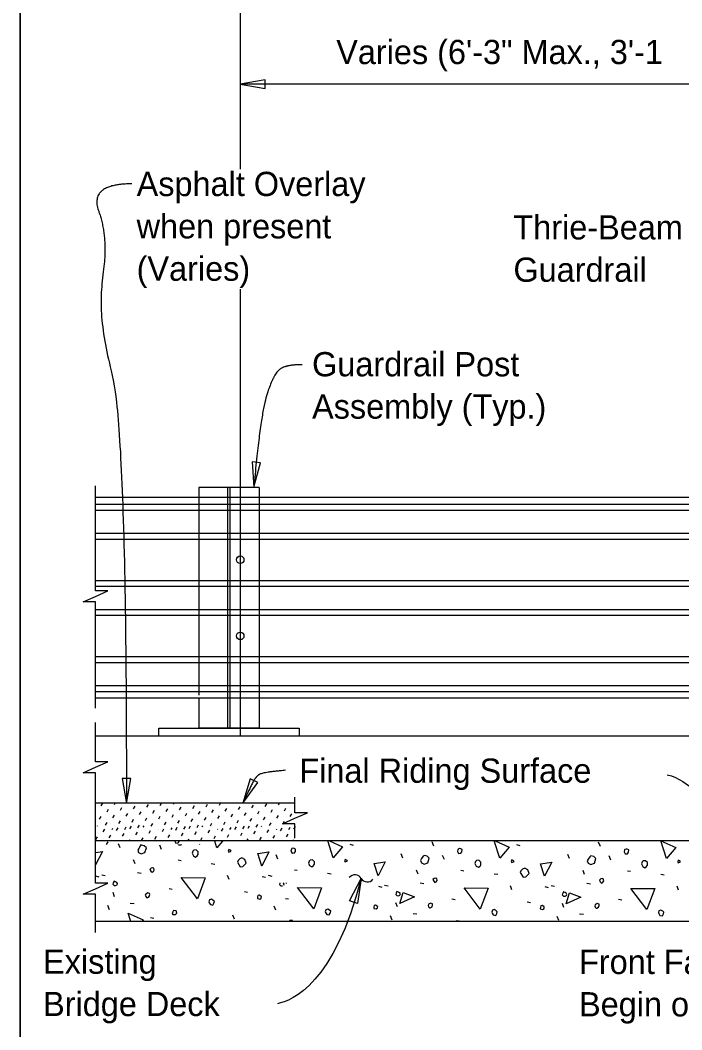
# Model space of a CAD drawing. Extents: x 0 to 41.1, y 0 to 25.9.
# Drawn here: x 0 to 5.5, y 5.42 to 13.82 of the extents above; entities that cross this region are included whole.
import ezdxf

# ---------------------------------------------------------------- set-up
doc = ezdxf.new("R2010")
doc.units = 0
for name, color, linetype in [('Dimension', 7, 'Continuous'), ('ExistSuperStruct', 7, 'Continuous'), ('Miscellaneous', 7, 'Continuous'), ('Miscellaneous1', 7, 'Continuous'), ('SteelMisc', 7, 'Continuous'), ('SteelMisc_h', 7, 'Continuous'), ('TextStructures', 7, 'Continuous')]:
    doc.layers.add(name, color=color, linetype=linetype)

msp = doc.modelspace()

# ---------------------------------------------------------------- linework, layer by layer
at = {"layer": 'Dimension'}
msp.add_line((13.3576, 13.2855), (1.8291, 13.2855), dxfattribs=at)
for points in [[(0, 0), (41.0506, 0), (41.0506, 25.9461), (0, 25.9461)], [(1.8291, 13.2855), (2.0373, 13.2502), (2.0373, 13.3208)], [(1.9418, 9.9338), (1.9976, 10.1375), (1.9274, 10.1445)], [(0.884, 7.306), (0.9193, 7.5143), (0.8488, 7.5143)], [(1.8496, 7.3086), (1.9742, 7.4791), (1.9111, 7.5107)], [(2.8349, 6.682), (2.8044, 6.473), (2.7373, 6.4947)]]:
    msp.add_lwpolyline(points, close=True, dxfattribs=at)
for points in [[(0.6262, 8.0985), (0.6262, 8.9817), (0.5229, 8.9817), (0.6262, 9.0267), (0.7296, 9.0717), (0.6262, 9.0717), (0.6262, 9.9446)], [(0.6262, 6.994), (0.6262, 7.5611), (0.5229, 7.5611), (0.6262, 7.6061), (0.7296, 7.6511), (0.6262, 7.6511), (0.6262, 7.9771)], [(2.2842, 7.0165), (2.2842, 7.1374), (2.1809, 7.1374), (2.2842, 7.1824), (2.3875, 7.2274), (2.2842, 7.2274), (2.2842, 7.358)], [(0.6262, 6.2316), (0.6262, 6.5516), (0.5229, 6.5516), (0.6262, 6.5966), (0.7296, 6.6416), (0.6262, 6.6416), (0.6262, 6.994)]]:
    msp.add_lwpolyline(points, dxfattribs=at)
for centre, start, end in [((2.7825, 6.6524), 30.00813, 141.73535), ((2.8857, 6.712), 210.00813, 321.73535)]:
    msp.add_arc(centre, 0.0596, start, end, dxfattribs=at)
for points, degree in [([(0.9269, 12.4562), (0.5696, 12.4558), (0.7356, 11.9999), (0.6366, 11.3563), (0.884, 10.4229), (0.884, 7.306)], 2), ([(2.3429, 10.9528), (2.2028, 10.9528), (2.1032, 10.8686), (1.9973, 10.5383), (1.9418, 9.9338)], 2), ([(2.2058, 7.581), (2.0322, 7.5656), (1.958, 7.5342), (1.8924, 7.3943), (1.8495, 7.3086)], 2), ([(5.3781, 7.5447), (5.4744, 7.5208), (5.6296, 7.4038), (5.7185, 7.3059), (5.9286, 6.9969)], 3), ([(2.834, 6.6822), (2.6134, 5.8085), (2.2614, 5.6668), (2.1395, 5.6403)], 3)]:
    msp.add_open_spline(points, degree=degree, dxfattribs=at)
at = {"layer": 'ExistSuperStruct'}
for p, q in [((0.6262, 7.8689), (8.9932, 7.8689)), ((2.2842, 7.3073), (0.6262, 7.3073)), ((8.9932, 6.994), (0.6262, 6.994)), ((0.6262, 6.3273), (8.9932, 6.3273))]:
    msp.add_line(p, q, dxfattribs=at)
at = {"layer": 'Miscellaneous'}
for p, q in [((1.8291, 15.3365), (1.8291, 12.5773)), ((1.8291, 11.5818), (1.8291, 7.8713)), ((0.6731, 7.2848), (0.6861, 7.3072)), ((0.7838, 7.2978), (0.7893, 7.3073)), ((1.1645, 7.2878), (1.1758, 7.3073)), ((1.2751, 7.3008), (1.2789, 7.3073)), ((1.6559, 7.2909), (1.6654, 7.3073)), ((1.7665, 7.3038), (1.7685, 7.3073)), ((2.0366, 7.2809), (2.0495, 7.3033)), ((2.1472, 7.2939), (2.155, 7.3073)), ((2.2579, 7.3068), (2.2581, 7.3073)), ((0.722, 7.236), (0.7349, 7.2584)), ((0.8326, 7.2489), (0.8456, 7.2713)), ((0.8814, 7.2001), (0.8944, 7.2225)), ((0.9432, 7.2619), (0.9562, 7.2843)), ((0.9921, 7.2131), (1.005, 7.2355)), ((1.0539, 7.2749), (1.0668, 7.2973)), ((1.1027, 7.226), (1.1157, 7.2484)), ((1.2133, 7.239), (1.2263, 7.2614)), ((1.324, 7.252), (1.3369, 7.2744)), ((1.3728, 7.2031), (1.3858, 7.2255)), ((1.4346, 7.2649), (1.4476, 7.2873)), ((1.4834, 7.2161), (1.4964, 7.2385)), ((1.5452, 7.2779), (1.5582, 7.3003)), ((1.5941, 7.2291), (1.607, 7.2515)), ((1.7047, 7.242), (1.7177, 7.2644)), ((1.8153, 7.255), (1.8283, 7.2774)), ((1.8642, 7.2062), (1.8771, 7.2285)), ((1.926, 7.268), (1.9389, 7.2903)), ((1.9748, 7.2191), (1.9878, 7.2415)), ((2.0854, 7.2321), (2.0984, 7.2545)), ((2.1961, 7.245), (2.209, 7.2674)), ((2.2449, 7.1962), (2.2579, 7.2186)), ((0.6602, 7.1742), (0.6731, 7.1966)), ((0.709, 7.1254), (0.722, 7.1477)), ((0.7708, 7.1872), (0.7838, 7.2095)), ((0.8196, 7.1383), (0.8326, 7.1607)), ((0.9303, 7.1513), (0.9432, 7.1737)), ((1.0409, 7.1642), (1.0539, 7.1866)), ((1.0897, 7.1154), (1.1027, 7.1378)), ((1.1515, 7.1772), (1.1645, 7.1996)), ((1.2004, 7.1284), (1.2133, 7.1508)), ((1.2622, 7.1902), (1.2751, 7.2126)), ((1.311, 7.1413), (1.324, 7.1637)), ((1.4216, 7.1543), (1.4346, 7.1767)), ((1.5323, 7.1673), (1.5452, 7.1897)), ((1.5811, 7.1184), (1.5941, 7.1408)), ((1.6429, 7.1802), (1.6559, 7.2026)), ((1.6917, 7.1314), (1.7047, 7.1538)), ((1.7535, 7.1932), (1.7665, 7.2156)), ((1.8024, 7.1444), (1.8153, 7.1667)), ((1.913, 7.1573), (1.926, 7.1797)), ((2.0236, 7.1703), (2.0366, 7.1927)), ((2.0725, 7.1214), (2.0854, 7.1438)), ((2.1343, 7.1832), (2.1472, 7.2056)), ((2.1831, 7.1344), (2.1961, 7.1568)), ((2.2937, 7.1474), (2.2938, 7.1476)), ((0.6419, 7.1175), (0.6427, 7.119)), ((0.6907, 7.0686), (0.7037, 7.091)), ((0.7647, 7.0883), (0.7708, 7.0989)), ((0.8013, 7.0816), (0.8143, 7.104)), ((0.8502, 7.0328), (0.8631, 7.0551)), ((0.8685, 7.0895), (0.8814, 7.1119)), ((0.912, 7.0945), (0.9249, 7.1169)), ((0.9608, 7.0457), (0.9738, 7.0681)), ((0.9791, 7.1024), (0.9921, 7.1248)), ((1.0226, 7.1075), (1.0292, 7.119)), ((1.0714, 7.0587), (1.0844, 7.0811)), ((1.1512, 7.0883), (1.1515, 7.089)), ((1.1821, 7.0716), (1.195, 7.094)), ((1.2543, 7.0883), (1.2622, 7.1019)), ((1.2927, 7.0846), (1.3056, 7.107)), ((1.3415, 7.0358), (1.3545, 7.0582)), ((1.3598, 7.0925), (1.3728, 7.1149)), ((1.4033, 7.0976), (1.4157, 7.119)), ((1.4522, 7.0487), (1.4651, 7.0711)), ((1.4705, 7.1055), (1.4834, 7.1279)), ((1.514, 7.1105), (1.5188, 7.119)), ((1.5628, 7.0617), (1.5757, 7.0841)), ((1.6408, 7.0883), (1.6429, 7.092)), ((1.6734, 7.0747), (1.6864, 7.0971)), ((1.7439, 7.0883), (1.7535, 7.105)), ((1.7841, 7.0876), (1.797, 7.11)), ((1.8329, 7.0388), (1.8458, 7.0612)), ((1.8512, 7.0955), (1.8642, 7.1179)), ((1.8947, 7.1006), (1.9053, 7.119)), ((1.9435, 7.0518), (1.9565, 7.0741)), ((1.9618, 7.1085), (1.9748, 7.1309)), ((2.0053, 7.1136), (2.0085, 7.119)), ((2.0542, 7.0647), (2.0671, 7.0871)), ((2.1304, 7.0883), (2.1343, 7.095)), ((2.1648, 7.0777), (2.1777, 7.1001)), ((2.2136, 7.0288), (2.2266, 7.0512)), ((2.2335, 7.0883), (2.2449, 7.108)), ((2.2754, 7.0906), (2.2884, 7.113)), ((0.6289, 7.0068), (0.6419, 7.0292)), ((0.7184, 6.9645), (0.7314, 6.9869)), ((0.7395, 7.0198), (0.7525, 7.0422)), ((0.8301, 6.9357), (0.816, 6.971)), ((0.9048, 6.994), (0.912, 7.0063)), ((1.0096, 6.9969), (1.0226, 7.0193)), ((1.1203, 7.0098), (1.1332, 7.0322)), ((1.2309, 7.0228), (1.2439, 7.0452)), ((1.2913, 6.994), (1.2927, 6.9964)), ((1.3944, 6.994), (1.4033, 7.0093)), ((1.4908, 6.9633), (1.4929, 6.967)), ((1.501, 6.9999), (1.514, 7.0223)), ((1.6116, 7.0129), (1.6246, 7.0353)), ((1.7223, 7.0258), (1.7352, 7.0482)), ((1.7809, 6.994), (1.7841, 6.9994)), ((1.884, 6.994), (1.8947, 7.0123)), ((1.9924, 7.0029), (2.0053, 7.0253)), ((2.103, 7.0159), (2.1159, 7.0383)), ((2.2705, 6.994), (2.2754, 7.0024)), ((2.7398, 6.9668), (2.768, 6.9598)), ((3.438, 6.9509), (3.4239, 6.9863)), ((4.8227, 6.9474), (4.8086, 6.9827)), ((1.0011, 6.9633), (1.0015, 6.964)), ((1.1742, 6.9239), (1.16, 6.9593)), ((3.1817, 6.8502), (3.1676, 6.8855)), ((4.1244, 6.9633), (4.1527, 6.9562)), ((0.9556, 6.8031), (0.9432, 6.8367)), ((1.3121, 6.8356), (1.3368, 6.832)), ((1.5878, 6.8073), (1.6179, 6.802)), ((2.1411, 6.8419), (2.127, 6.8773)), ((3.5258, 6.8384), (3.5116, 6.8738)), ((4.5664, 6.8466), (4.5522, 6.882)), ((4.9105, 6.8349), (4.8963, 6.8702)), ((0.9744, 6.7313), (1.0045, 6.7259)), ((2.279, 6.7536), (2.3037, 6.75)), ((2.5548, 6.7253), (2.5848, 6.72)), ((3.3072, 6.7176), (3.2948, 6.7512)), ((3.6637, 6.75), (3.6884, 6.7465)), ((3.9394, 6.7217), (3.9695, 6.7164)), ((4.6919, 6.714), (4.6795, 6.7476)), ((5.0483, 6.7465), (5.0731, 6.7429)), ((5.3241, 6.7182), (5.3542, 6.7129)), ((0.6257, 6.703), (0.6539, 6.6959)), ((0.6781, 6.7129), (0.7064, 6.7059)), ((1.7363, 6.6729), (1.724, 6.7065)), ((2.0103, 6.6994), (2.0386, 6.6924)), ((2.0627, 6.7094), (2.091, 6.7023)), ((3.326, 6.6457), (3.3561, 6.6404)), ((4.7107, 6.6422), (4.7408, 6.6369)), ((0.7841, 6.5304), (0.7718, 6.5639)), ((1.2378, 6.5987), (1.2643, 6.5934)), ((1.8636, 6.5739), (1.8901, 6.5686)), ((2.9773, 6.6174), (3.0055, 6.6104)), ((3.0297, 6.6274), (3.058, 6.6203)), ((4.0879, 6.5874), (4.0756, 6.621)), ((4.3619, 6.6139), (4.3902, 6.6068)), ((4.4143, 6.6239), (4.4426, 6.6168)), ((5.4726, 6.5838), (5.4602, 6.6174)), ((0.9143, 6.4767), (0.9461, 6.4732)), ((2.2047, 6.5167), (2.2313, 6.5114)), ((3.1357, 6.4448), (3.1234, 6.4784)), ((3.5894, 6.5131), (3.6159, 6.5078)), ((4.2152, 6.4884), (4.2417, 6.4831)), ((4.5204, 6.4413), (4.508, 6.4749)), ((4.9741, 6.5096), (5.0006, 6.5043)), ((0.7417, 6.4208), (0.7276, 6.4561)), ((2.1264, 6.4172), (2.1122, 6.4526)), ((3.2659, 6.3912), (3.2977, 6.3876)), ((4.6506, 6.3876), (4.6824, 6.3841)), ((1.0823, 6.3583), (1.1105, 6.3512)), ((1.7805, 6.3423), (1.7664, 6.3777)), ((3.0933, 6.3352), (3.0792, 6.3706)), ((4.478, 6.3317), (4.4638, 6.367))]:
    msp.add_line(p, q, dxfattribs=at)
for points in [[(1.2841, 6.9906), (1.2926, 6.9752), (1.3121, 6.977), (1.3209, 6.9893), (1.321, 6.9906)], [(1.6356, 6.9363), (1.6179, 6.9906)], [(1.6815, 6.9906), (1.6356, 6.9363)], [(2.6025, 6.8543), (2.5571, 6.994)], [(2.5709, 6.994), (2.6803, 6.9462), (2.6025, 6.8543)], [(3.9872, 6.8508), (3.9406, 6.994)], [(3.9475, 6.994), (4.065, 6.9427), (3.9872, 6.8508)], [(5.3718, 6.8472), (5.3241, 6.994), (5.4496, 6.9392), (5.3718, 6.8472)], [(0.6262, 6.8981), (0.6834, 6.9056), (0.6262, 6.7947)], [(0.9839, 6.8986), (1.0069, 6.8862), (1.0369, 6.8986), (1.0493, 6.9357), (1.0316, 6.9534), (1.0086, 6.9587), (0.998, 6.9516), (0.9857, 6.9322), (0.9768, 6.9162), (0.9839, 6.8986)], [(1.3161, 6.9633), (1.3172, 6.9609), (1.3148, 6.9633)], [(1.3172, 6.9609), (1.3384, 6.9609), (1.3408, 6.9633)], [(1.4287, 6.8921), (1.4394, 6.8709), (1.457, 6.8603), (1.4712, 6.8709), (1.4782, 6.8815), (1.4782, 6.9027), (1.4623, 6.9186), (1.4429, 6.9169), (1.434, 6.908), (1.4287, 6.8921)], [(1.7346, 6.901), (1.754, 6.9098), (1.7469, 6.9169), (1.7346, 6.9222), (1.7293, 6.9098), (1.7346, 6.901)], [(2.0079, 6.7854), (1.9744, 6.8897), (2.0681, 6.9021), (2.0079, 6.7854)], [(2.2507, 6.9091), (2.2595, 6.8932), (2.279, 6.895), (2.2878, 6.9073), (2.2896, 6.9268), (2.2772, 6.9321), (2.2684, 6.9339), (2.2578, 6.9303), (2.2542, 6.9268), (2.2507, 6.9091)], [(3.6354, 6.9056), (3.6442, 6.8897), (3.6637, 6.8914), (3.6725, 6.9038), (3.6743, 6.9233), (3.6619, 6.9286), (3.6531, 6.9303), (3.6425, 6.9268), (3.6389, 6.9233), (3.6354, 6.9056)], [(5.0201, 6.902), (5.0289, 6.8861), (5.0483, 6.8879), (5.0572, 6.9003), (5.059, 6.9197), (5.0466, 6.925), (5.0377, 6.9268), (5.0271, 6.9233), (5.0236, 6.9197), (5.0201, 6.902)], [(1.8053, 6.8161), (1.8283, 6.779), (1.8512, 6.7807), (1.8601, 6.7896), (1.8795, 6.809), (1.8672, 6.8391), (1.8424, 6.8532), (1.8247, 6.8462), (1.8106, 6.832), (1.8053, 6.8161)], [(2.3957, 6.8101), (2.4063, 6.7889), (2.4239, 6.7783), (2.4381, 6.7889), (2.4452, 6.7995), (2.4452, 6.8207), (2.4293, 6.8366), (2.4098, 6.8349), (2.401, 6.826), (2.3957, 6.8101)], [(2.7015, 6.819), (2.7209, 6.8278), (2.7139, 6.8349), (2.7015, 6.8402), (2.6962, 6.8278), (2.7015, 6.819)], [(2.9749, 6.7034), (2.9413, 6.8077), (3.035, 6.8201), (2.9749, 6.7034)], [(3.3355, 6.813), (3.3585, 6.8007), (3.3885, 6.813), (3.4009, 6.8502), (3.3832, 6.8678), (3.3602, 6.8731), (3.3496, 6.8661), (3.3373, 6.8466), (3.3284, 6.8307), (3.3355, 6.813)], [(3.7803, 6.8066), (3.7909, 6.7854), (3.8086, 6.7748), (3.8228, 6.7854), (3.8298, 6.796), (3.8298, 6.8172), (3.8139, 6.8331), (3.7945, 6.8313), (3.7856, 6.8225), (3.7803, 6.8066)], [(4.0862, 6.8154), (4.1056, 6.8243), (4.0985, 6.8313), (4.0862, 6.8366), (4.0809, 6.8243), (4.0862, 6.8154)], [(4.3595, 6.6999), (4.326, 6.8042), (4.4196, 6.8166), (4.3595, 6.6999)], [(4.7202, 6.8095), (4.7431, 6.7971), (4.7732, 6.8095), (4.7856, 6.8466), (4.7679, 6.8643), (4.7449, 6.8696), (4.7343, 6.8625), (4.7219, 6.8431), (4.7131, 6.8272), (4.7202, 6.8095)], [(5.165, 6.803), (5.1756, 6.7818), (5.1933, 6.7712), (5.2074, 6.7818), (5.2145, 6.7924), (5.2145, 6.8137), (5.1986, 6.8296), (5.1792, 6.8278), (5.1703, 6.819), (5.165, 6.803)], [(5.4708, 6.8119), (5.4903, 6.8207), (5.4832, 6.8278), (5.4708, 6.8331), (5.4655, 6.8207), (5.4708, 6.8119)], [(1.0858, 6.7436), (1.0964, 6.733), (1.107, 6.7401), (1.1141, 6.7507), (1.1105, 6.7684), (1.1017, 6.7701), (1.0893, 6.7684), (1.0787, 6.7578), (1.0858, 6.7436)], [(4.1569, 6.7306), (4.1799, 6.6934), (4.2028, 6.6952), (4.2117, 6.7041), (4.2311, 6.7235), (4.2187, 6.7536), (4.194, 6.7677), (4.1763, 6.7606), (4.1622, 6.7465), (4.1569, 6.7306)], [(0.7806, 6.6246), (0.793, 6.6228), (0.8053, 6.6281), (0.8089, 6.6387), (0.8036, 6.6475), (0.793, 6.6546), (0.7806, 6.6599), (0.7735, 6.6458), (0.77, 6.6352), (0.7806, 6.6246)], [(1.4729, 6.512), (1.3386, 6.6888), (1.5383, 6.6871), (1.4729, 6.512)], [(2.1596, 6.6451), (2.1582, 6.6422), (2.1547, 6.6316), (2.1653, 6.621)], [(2.1909, 6.6271), (2.1936, 6.6352), (2.1883, 6.644), (2.1867, 6.6451)], [(2.2138, 6.6412), (2.215, 6.6451)], [(3.4374, 6.6581), (3.448, 6.6475), (3.4586, 6.6546), (3.4657, 6.6652), (3.4621, 6.6828), (3.4533, 6.6846), (3.4409, 6.6828), (3.4303, 6.6722), (3.4374, 6.6581)], [(4.8221, 6.6546), (4.8327, 6.6439), (4.8433, 6.651), (4.8504, 6.6616), (4.8468, 6.6793), (4.838, 6.6811), (4.8256, 6.6793), (4.815, 6.6687), (4.8221, 6.6546)], [(1.0504, 6.5244), (1.0575, 6.5244), (1.0717, 6.5315), (1.077, 6.5474), (1.0752, 6.5562), (1.061, 6.5633), (1.0434, 6.5527), (1.0398, 6.5421), (1.0434, 6.5315), (1.0504, 6.5244)], [(2.1653, 6.621), (2.1777, 6.6193), (2.1795, 6.6201)], [(2.4399, 6.43), (2.3055, 6.6068), (2.5053, 6.6051), (2.4399, 6.43)], [(3.1322, 6.539), (3.1446, 6.5373), (3.1569, 6.5426), (3.1605, 6.5532), (3.1552, 6.562), (3.1446, 6.5691), (3.1322, 6.5744), (3.1251, 6.5602), (3.1216, 6.5496), (3.1322, 6.539)], [(3.1546, 6.4742), (3.1828, 6.5662), (3.2765, 6.529), (3.1546, 6.4742)], [(3.8245, 6.4265), (3.6902, 6.6033), (3.8899, 6.6015), (3.8245, 6.4265)], [(4.5169, 6.5355), (4.5292, 6.5337), (4.5416, 6.539), (4.5452, 6.5496), (4.5399, 6.5585), (4.5292, 6.5655), (4.5169, 6.5708), (4.5098, 6.5567), (4.5063, 6.5461), (4.5169, 6.5355)], [(4.5392, 6.4707), (4.5675, 6.5626), (4.6612, 6.5255), (4.5392, 6.4707)], [(5.2092, 6.423), (5.0749, 6.5998), (5.2746, 6.598), (5.2092, 6.423)], [(1.5719, 6.4802), (1.5808, 6.4643), (1.602, 6.4608), (1.6108, 6.4767), (1.6144, 6.4908), (1.6055, 6.4997), (1.5896, 6.5085), (1.5737, 6.5032), (1.5684, 6.4873), (1.5719, 6.4802)], [(1.9714, 6.5156), (1.9909, 6.5103), (2.0033, 6.5191), (2.005, 6.5315), (2.0015, 6.535), (1.9874, 6.5421), (1.975, 6.5403), (1.9732, 6.528), (1.9714, 6.5156)], [(3.402, 6.4389), (3.4091, 6.4389), (3.4233, 6.446), (3.4286, 6.4619), (3.4268, 6.4707), (3.4126, 6.4778), (3.395, 6.4672), (3.3914, 6.4566), (3.395, 6.446), (3.402, 6.4389)], [(4.7867, 6.4354), (4.7938, 6.4354), (4.8079, 6.4424), (4.8132, 6.4583), (4.8115, 6.4672), (4.7973, 6.4742), (4.7796, 6.4636), (4.7761, 6.453), (4.7796, 6.4424), (4.7867, 6.4354)], [(0.9196, 6.324), (0.8973, 6.3925), (1.0228, 6.3377), (1.0112, 6.324)], [(1.2696, 6.383), (1.2909, 6.383), (1.3015, 6.3936), (1.2962, 6.4131), (1.2732, 6.4148), (1.2696, 6.4042), (1.2643, 6.3954), (1.2696, 6.383), (1.2661, 6.3865)], [(2.5389, 6.3982), (2.5477, 6.3823), (2.5689, 6.3788), (2.5777, 6.3947), (2.5813, 6.4088), (2.5724, 6.4177), (2.5565, 6.4265), (2.5406, 6.4212), (2.5353, 6.4053), (2.5389, 6.3982)], [(2.9384, 6.4336), (2.9578, 6.4283), (2.9702, 6.4371), (2.972, 6.4495), (2.9684, 6.453), (2.9543, 6.4601), (2.9419, 6.4583), (2.9401, 6.446), (2.9384, 6.4336)], [(3.9235, 6.3947), (3.9324, 6.3788), (3.9536, 6.3752), (3.9624, 6.3912), (3.966, 6.4053), (3.9571, 6.4141), (3.9412, 6.423), (3.9253, 6.4177), (3.92, 6.4018), (3.9235, 6.3947)], [(4.323, 6.43), (4.3425, 6.4247), (4.3549, 6.4336), (4.3566, 6.446), (4.3531, 6.4495), (4.339, 6.4566), (4.3266, 6.4548), (4.3248, 6.4424), (4.323, 6.43)], [(5.3082, 6.3912), (5.317, 6.3752), (5.3383, 6.3717), (5.3471, 6.3876), (5.3506, 6.4018), (5.3418, 6.4106), (5.3259, 6.4194), (5.31, 6.4141), (5.3047, 6.3982), (5.3082, 6.3912)], [(2.2641, 6.3273), (2.2631, 6.3311), (2.2401, 6.3328), (2.2383, 6.3273)], [(3.6478, 6.3273), (3.6478, 6.3275), (3.6248, 6.3293), (3.6241, 6.3273)]]:
    msp.add_lwpolyline(points, dxfattribs=at)
at = {"layer": 'Miscellaneous1'}
msp.add_lwpolyline([(0, 25.9461), (41.0506, 25.9461), (41.0506, 0), (0, 0)], close=True, dxfattribs=at)
at = {"layer": 'SteelMisc'}
for p, q in [((1.9853, 9.9315), (1.4853, 9.9315)), ((1.4853, 9.9315), (1.4853, 9.8482)), ((1.9853, 9.9315), (1.9853, 9.8482)), ((7.6624, 9.8481), (0.6262, 9.8481)), ((0.6262, 9.7926), (7.6624, 9.7926)), ((0.6262, 9.7444), (7.6624, 9.7444)), ((0.6262, 9.5515), (7.6624, 9.5515)), ((0.6262, 9.5033), (7.6624, 9.5033)), ((0.6262, 9.1594), (7.6624, 9.1594)), ((0.6262, 9.1111), (7.6624, 9.1111)), ((0.6262, 8.9183), (7.6624, 8.9183)), ((0.6262, 8.8702), (7.6624, 8.8702)), ((0.6262, 8.5262), (7.6624, 8.5262)), ((0.6262, 8.478), (7.6624, 8.478)), ((0.6262, 8.2852), (7.6624, 8.2852)), ((0.6262, 8.237), (7.6624, 8.237)), ((7.6624, 8.1814), (0.6262, 8.1814)), ((1.4853, 8.1814), (1.4853, 7.9315)), ((1.9853, 8.1814), (1.9853, 7.9315)), ((1.9853, 8.0982), (1.9853, 7.9315)), ((1.152, 7.9315), (2.3186, 7.9315)), ((1.152, 7.869), (1.152, 7.9315)), ((1.9853, 7.9315), (1.4853, 7.9315)), ((1.4853, 7.9315), (1.9853, 7.9315)), ((2.3186, 7.9315), (2.3186, 7.869)), ((1.152, 7.869), (2.3186, 7.869))]:
    msp.add_line(p, q, dxfattribs=at)
for centre in [(1.8291, 9.3314), (1.8291, 8.6983)]:
    msp.add_circle(centre, 0.0312, dxfattribs=at)
at = {"layer": 'SteelMisc_h'}
for p, q in [((1.7249, 7.9315), (1.7249, 9.9315)), ((1.7457, 7.9315), (1.7457, 9.9315)), ((1.4853, 9.8481), (1.4853, 8.2046)), ((1.9853, 9.8481), (1.9853, 8.1814))]:
    msp.add_line(p, q, dxfattribs=at)

# ---------------------------------------------------------------- texts
at = {"layer": 'Dimension'}
for s, p in [('Asphalt Overlay', (0.968, 12.3548)), ('when present', (0.968, 12.0028)), ('Thrie-Beam ', (4.1001, 11.994)), ('(Varies)', (0.968, 11.6508)), ('Guardrail', (4.1001, 11.642)), ('Guardrail Post ', (2.4263, 10.8562)), ('Assembly (Typ.)', (2.4263, 10.5042)), ('Existing ', (0.1904, 5.8896)), ('Front Face of Backwall &', (4.6456, 5.8873)), ('Bridge Deck', (0.1904, 5.5376)), ('Begin or End Bridge', (4.6456, 5.5353))]:
    msp.add_text(s, height=0.2016, dxfattribs=at).set_placement(p)
at = {"layer": 'TextStructures'}
for s, p in [('Varies (6\'-3" Max., 3\'-1', (2.627, 13.4517)), ('Final Riding Surface', (2.3205, 7.4773))]:
    msp.add_text(s, height=0.2016, dxfattribs=at).set_placement(p)

doc.saveas('drawing.dxf')
